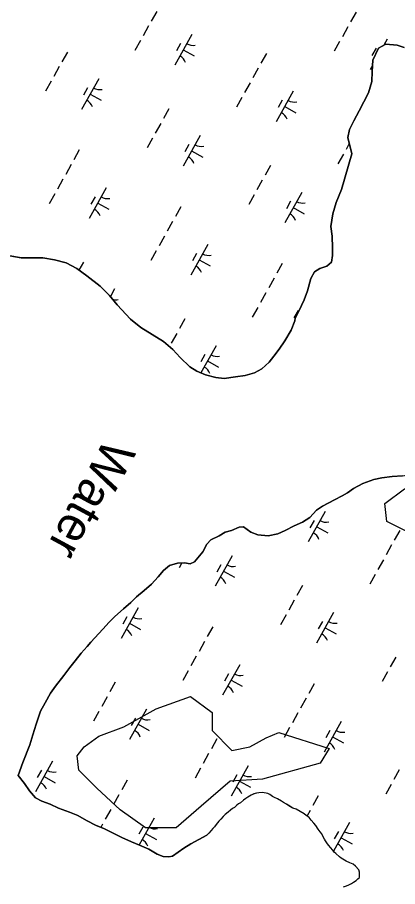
# Model space of a CAD drawing. Extents: x 3923531 to 3943530, y 207391 to 229799.
# Drawn here: x 3935760 to 3936304, y 215274 to 216516 of the extents above; entities that cross this region are included whole.
import ezdxf

# ---------------------------------------------------------------- set-up
doc = ezdxf.new("R2010")
doc.units = 0
for name, color, linetype in [('V-GRID-MAJR', 7, 'Continuous'), ('V-RIVR-IDEN', 7, 'Continuous'), ('V-SITE-VEGE', 7, 'Continuous'), ('V-TOPO-SHOR', 7, 'Continuous'), ('V-WETL-SWMP', 7, 'Continuous')]:
    doc.layers.add(name, color=color, linetype=linetype)

msp = doc.modelspace()

# ---------------------------------------------------------------- linework, layer by layer
at = {"layer": 'V-GRID-MAJR'}
msp.add_spline([(3935779.9, 210874.8), (3935760.8, 211942.6), (3935652.4, 218002.6), (3935544, 224062.6), (3935501.8, 226418.9)], degree=3, dxfattribs=at)
at = {"layer": 'V-SITE-VEGE'}
for points in [[(3936450.2, 215860.4), (3936491.4, 215845), (3936501.7, 215834.7), (3936524.9, 215826.9), (3936548.1, 215824.3), (3936571.2, 215829.5), (3936599.6, 215842.4), (3936620.2, 215821.8), (3936612.4, 215798.6), (3936589.3, 215785.7), (3936550.6, 215772.8), (3936522.3, 215749.6), (3936486.3, 215729), (3936442.5, 215726.4), (3936419.3, 215739.3), (3936367.8, 215759.9), (3936329.2, 215775.4), (3936288, 215796), (3936285.4, 215821.8), (3936313.7, 215842.4), (3936336.9, 215845), (3936393.6, 215842.4)], [(3936066.6, 215468.8), (3936092.3, 215474), (3936115.5, 215486.9), (3936133.5, 215494.6), (3936205.6, 215471.4), (3936192.7, 215450.8), (3936110.3, 215427.6), (3936064, 215425), (3936022.8, 215389), (3935986.7, 215358), (3935943, 215358), (3935906.9, 215383.8), (3935873.4, 215414.7), (3935847.7, 215440.5), (3935845.1, 215461.1), (3935855.4, 215474), (3935876, 215489.4), (3935912.1, 215502.3), (3935958.4, 215528.1), (3936007.3, 215546.1), (3936038.2, 215522.9), (3936038.2, 215497.2)]]:
    msp.add_lwpolyline(points, close=True, dxfattribs=at)
at = {"layer": 'V-TOPO-SHOR'}
for points in [[(3936313.1, 216473.2), (3936303, 216476.7), (3936286.8, 216478.2), (3936276.2, 216472.6), (3936268.1, 216455.3), (3936267.3, 216438.8), (3936266.7, 216424.8), (3936262, 216408.5), (3936255.3, 216395.8), (3936248.6, 216382.6), (3936240.8, 216368.3), (3936234.9, 216356.2), (3936232.2, 216344.8), (3936238.2, 216321.3), (3936223.5, 216270.6), (3936215.7, 216251.9), (3936210.8, 216235.4), (3936208.2, 216217.7), (3936210, 216203.9), (3936210.5, 216187)], [(3936210.5, 216187), (3936210.5, 216176.2), (3936209, 216166.5), (3936202.4, 216160.8), (3936192.6, 216157.3), (3936184.6, 216152.8), (3936179.5, 216143.2), (3936174.5, 216125.4), (3936170, 216112.6), (3936162.3, 216096.4), (3936157.2, 216086.3), (3936156.5, 216082.5), (3936151.4, 216069.2), (3936142.3, 216054.1), (3936134.4, 216042.4), (3936126.7, 216032), (3936119.7, 216023.7), (3936109.2, 216014.2), (3936099, 216008.5), (3936085.6, 216004.5), (3936071.8, 216002.6), (3936055.6, 216000.4), (3936043.5, 216001.5), (3936029, 216005.7), (3936016.3, 216010.6), (3936006.5, 216016.9), (3935992.7, 216030.4), (3935982.1, 216041.8), (3935968.8, 216053.1), (3935952.4, 216063.3), (3935936.4, 216073.4), (3935921.3, 216085.1), (3935902.4, 216105.4), (3935891.4, 216118.9), (3935878.2, 216132.4), (3935859.2, 216146.8), (3935844.7, 216157.3), (3935829.7, 216165.4), (3935812.8, 216169.8), (3935795.9, 216172.7), (3935780.5, 216172.9), (3935765.4, 216172.9), (3935749, 216175.8)], [(3936310.8, 215861.3), (3936295.8, 215860.4), (3936281.1, 215858.4), (3936269.7, 215855.9), (3936253.7, 215850.3), (3936240.6, 215843.2), (3936231.8, 215836.8), (3936224.4, 215832.8), (3936213.2, 215827), (3936196.1, 215817.8), (3936187.5, 215812.3), (3936178.2, 215801.6), (3936167.4, 215794.8), (3936155.8, 215789.7), (3936142.9, 215783.1), (3936132.1, 215778.4), (3936118.3, 215775.7), (3936103.6, 215776.7), (3936093.7, 215780.6), (3936083.2, 215788.3), (3936076.8, 215787.7), (3936066.2, 215783.3), (3936057, 215780.6), (3936048.2, 215775.7), (3936036.3, 215769.8), (3936030.9, 215763.7), (3936025, 215752.6), (3936013.3, 215738.3), (3936007.1, 215735.6), (3935998.7, 215736.9), (3935988.7, 215736.4), (3935977.5, 215732.9), (3935968.5, 215726.1), (3935961, 215716.8), (3935951.5, 215706.3), (3935941.3, 215697.2), (3935930, 215688.4), (3935921.8, 215680.1), (3935911.3, 215671.2), (3935899.2, 215660.4), (3935890.8, 215652.1), (3935881.9, 215642), (3935865, 215623.7), (3935859.3, 215617.3), (3935850.8, 215607.7), (3935842.4, 215597), (3935834.7, 215587.5), (3935826, 215576), (3935814.1, 215560.6), (3935807.2, 215550.5), (3935799.3, 215536.6), (3935792.8, 215524.7), (3935786.4, 215506.4), (3935781.7, 215491.3), (3935777.3, 215476.6), (3935767.7, 215451.4), (3935760.7, 215433)], [(3935760.7, 215433), (3935770.1, 215421.6), (3935777.1, 215411.1), (3935785.7, 215401.1), (3935794.5, 215396.5), (3935806.7, 215391.8), (3935818.7, 215386.5), (3935834.2, 215380.6), (3935846.4, 215375.6), (3935858.8, 215368.7), (3935872.6, 215361.5), (3935883.4, 215357), (3935897.5, 215350.2), (3935909.1, 215344.5), (3935922.9, 215338.4), (3935934.3, 215333.6), (3935947.7, 215327.7), (3935959.8, 215320.7), (3935968.3, 215317), (3935976.6, 215316.6), (3935981.7, 215317.5), (3935997.6, 215329.2), (3936007.6, 215335.2), (3936030.7, 215347.8)], [(3936248.9, 215291.8), (3936249.3, 215294.9), (3936248.2, 215298.1), (3936243.5, 215303.3), (3936240, 215306.1), (3936235.2, 215308.1), (3936230.1, 215310.6), (3936223, 215315), (3936220.3, 215316.6), (3936215.2, 215321.4), (3936212.8, 215323.4), (3936210.9, 215326.2), (3936207.8, 215330.2), (3936205.4, 215333), (3936203.5, 215335.4), (3936200.7, 215339.4), (3936199.2, 215342.1), (3936196.8, 215346.1), (3936195.3, 215349.7), (3936193, 215352.5), (3936190.2, 215356.5), (3936186.7, 215361.3), (3936184, 215364.8), (3936180.1, 215369.2), (3936176.9, 215372.8), (3936173, 215376), (3936169.9, 215378.1), (3936164.4, 215381.3), (3936158.5, 215384.9), (3936153.7, 215386.5), (3936149.4, 215388.9), (3936144.7, 215391.8), (3936140.4, 215394.2), (3936137.6, 215396.2), (3936131.7, 215399.4), (3936127.4, 215401.4), (3936124.6, 215403.1), (3936120.7, 215405.9), (3936117.9, 215407.1), (3936110.4, 215408.7), (3936105.3, 215408.4), (3936101.7, 215407.6), (3936098.1, 215406.9), (3936094.2, 215405), (3936089.4, 215401.8), (3936086.6, 215399.9), (3936083.4, 215397.9), (3936079, 215394), (3936076.2, 215392.5), (3936073.8, 215390.5), (3936070.2, 215387.4), (3936067.5, 215385.8), (3936064.7, 215383.5), (3936061.1, 215380.8), (3936057.1, 215377.2), (3936054.3, 215374.5), (3936050.7, 215370.6), (3936047.9, 215367.8), (3936044.3, 215363.1), (3936041.9, 215359.6), (3936039.1, 215357.2), (3936037.1, 215354.5), (3936033.5, 215350.6), (3936030.7, 215347.8)], [(3936226.2, 215273.8), (3936229, 215275), (3936232.9, 215276.1), (3936237.7, 215278.8), (3936240.5, 215280.4), (3936244.5, 215282.7), (3936246.9, 215285.1), (3936248.9, 215287.4), (3936248.9, 215291.8)]]:
    msp.add_lwpolyline(points, dxfattribs=at)
at = {"layer": 'V-WETL-SWMP'}
for p, q in [((3935959, 216525), (3935951.2, 216511)), ((3936244.2, 216523.8), (3936236.4, 216509.8)), ((3935947.3, 216504.1), (3935939.5, 216490.1)), ((3936232.5, 216502.8), (3936224.6, 216488.8)), ((3936009.2, 216491.9), (3935984.8, 216448.2)), ((3935935.6, 216483.1), (3935927.7, 216469.1)), ((3935993.2, 216479.1), (3935987.4, 216468.6)), ((3936220.7, 216481.9), (3936212.9, 216467.9)), ((3936276.2, 216472.6), (3936286.8, 216478.2)), ((3936288.8, 216485.4), (3936284, 216476.7)), ((3936286.8, 216478.2), (3936303, 216476.7)), ((3935831.3, 216466.9), (3935823.5, 216453)), ((3935997, 216470.1), (3936012.7, 216461.3)), ((3936272.8, 216472.6), (3936267, 216462.1)), ((3936268.1, 216455.3), (3936276.2, 216472.6)), ((3936303, 216476.7), (3936313.1, 216473.2)), ((3936115.9, 216464.8), (3936108.1, 216450.9)), ((3936267.3, 216438.8), (3936268.1, 216455.3)), ((3935819.6, 216446), (3935811.8, 216432)), ((3936104.2, 216443.9), (3936096.4, 216429.9)), ((3936267.7, 216447.6), (3936264.5, 216441.7)), ((3935876, 216428.6), (3935851.6, 216384.9)), ((3936266.7, 216424.8), (3936267.3, 216438.8)), ((3935807.9, 216425), (3935800.1, 216411.1)), ((3935860, 216415.7), (3935854.2, 216405.3)), ((3936092.5, 216422.9), (3936084.7, 216409)), ((3936262, 216408.5), (3936266.7, 216424.8)), ((3935863.8, 216406.7), (3935879.5, 216398)), ((3936154.4, 216410.8), (3936130, 216367.1)), ((3936255.3, 216395.8), (3936262, 216408.5)), ((3936080.8, 216402), (3936073, 216388)), ((3936138.4, 216397.9), (3936132.6, 216387.5)), ((3936248.6, 216382.6), (3936255.3, 216395.8)), ((3935976.6, 216385.8), (3935968.7, 216371.8)), ((3936142.2, 216388.9), (3936158, 216380.1)), ((3936240.8, 216368.3), (3936248.6, 216382.6)), ((3936234.9, 216356.2), (3936240.8, 216368.3)), ((3935964.8, 216364.9), (3935957, 216350.9)), ((3936232.2, 216344.8), (3936234.9, 216356.2)), ((3935953.1, 216343.9), (3935945.3, 216329.9)), ((3936021.2, 216347.4), (3935996.8, 216303.8)), ((3936238.2, 216321.3), (3936232.2, 216344.8)), ((3936005.2, 216334.6), (3935999.4, 216324.1)), ((3936234.4, 216336), (3936229.9, 216327.8)), ((3935848.3, 216326.9), (3935840.5, 216312.9)), ((3936009, 216325.6), (3936024.8, 216316.8)), ((3936226, 216320.9), (3936218.2, 216306.9)), ((3936223.5, 216270.6), (3936238.2, 216321.3)), ((3935836.6, 216305.9), (3935828.8, 216292)), ((3936121.8, 216304.7), (3936114, 216290.7)), ((3935824.9, 216285), (3935817.1, 216271)), ((3936110.1, 216283.7), (3936102.3, 216269.8)), ((3935886.8, 216272.8), (3935862.4, 216229.1)), ((3936166.4, 216266.3), (3936142.1, 216222.7)), ((3936215.7, 216251.9), (3936223.5, 216270.6)), ((3935813.2, 216264), (3935805.4, 216250.1)), ((3935870.8, 216260), (3935865, 216249.5)), ((3936098.4, 216262.8), (3936090.6, 216248.8)), ((3935874.6, 216251), (3935890.3, 216242.2)), ((3935993.5, 216245.8), (3935985.7, 216231.8)), ((3936150.4, 216253.5), (3936144.6, 216243)), ((3936154.3, 216244.5), (3936170, 216235.7)), ((3936210.8, 216235.4), (3936215.7, 216251.9)), ((3936208.2, 216217.7), (3936210.8, 216235.4)), ((3935981.8, 216224.8), (3935974, 216210.8)), ((3936210, 216203.9), (3936208.2, 216217.7)), ((3935970.1, 216203.9), (3935962.3, 216189.9)), ((3936032, 216191.7), (3936007.7, 216148)), ((3936210.5, 216187), (3936210, 216203.9)), ((3935958.4, 216182.9), (3935950.6, 216168.9)), ((3936210.5, 216176.2), (3936210.5, 216187)), ((3935749, 216175.8), (3935765.3, 216172.9)), ((3935765.3, 216172.9), (3935780.5, 216172.9)), ((3935780.5, 216172.9), (3935795.9, 216172.7)), ((3935795.9, 216172.7), (3935812.8, 216169.8)), ((3935812.8, 216169.8), (3935829.7, 216165.4)), ((3936016, 216178.8), (3936010.2, 216168.4)), ((3936019.8, 216169.8), (3936035.6, 216161.1)), ((3936209, 216166.5), (3936210.5, 216176.2)), ((3935829.7, 216165.4), (3935844.7, 216157.3)), ((3935844.7, 216157.3), (3935859.2, 216146.8)), ((3935854.2, 216166.7), (3935847.7, 216155.1)), ((3936138.7, 216164.6), (3936130.9, 216150.7)), ((3936184.6, 216152.8), (3936192.6, 216157.3)), ((3936192.6, 216157.3), (3936202.4, 216160.8)), ((3936202.4, 216160.8), (3936209, 216166.5)), ((3935859.2, 216146.8), (3935878.2, 216132.4)), ((3936127, 216143.7), (3936119.2, 216129.7)), ((3936174.5, 216125.4), (3936179.5, 216143.2)), ((3936179.5, 216143.2), (3936184.6, 216152.8)), ((3935878.2, 216132.4), (3935891.4, 216118.9)), ((3935891.4, 216118.9), (3935902.4, 216105.4)), ((3935898.8, 216128.4), (3935892.7, 216117.3)), ((3936115.3, 216122.7), (3936107.5, 216108.8)), ((3936170, 216112.6), (3936174.5, 216125.4)), ((3935902.4, 216105.4), (3935921.3, 216085.1)), ((3936162.3, 216096.4), (3936170, 216112.6)), ((3936103.6, 216101.8), (3936095.8, 216087.8)), ((3936161.2, 216097.7), (3936155.4, 216087.2)), ((3936157.2, 216086.3), (3936162.3, 216096.4)), ((3935921.3, 216085.1), (3935936.4, 216073.4)), ((3935999.4, 216085.6), (3935991.6, 216071.6)), ((3936151.4, 216069.2), (3936156.5, 216082.5)), ((3936156.5, 216082.5), (3936157.2, 216086.3)), ((3935936.4, 216073.4), (3935952.4, 216063.3)), ((3936142.3, 216054.1), (3936151.4, 216069.2)), ((3935952.4, 216063.3), (3935968.8, 216053.1)), ((3935987.7, 216064.6), (3935979.9, 216050.7)), ((3935968.8, 216053.1), (3935982.1, 216041.8)), ((3936044.1, 216047.2), (3936022.3, 216008.2)), ((3936134.4, 216042.4), (3936142.3, 216054.1)), ((3935982.1, 216041.8), (3935992.7, 216030.4)), ((3935992.7, 216030.4), (3936006.5, 216016.9)), ((3936028, 216034.4), (3936022.2, 216023.9)), ((3936119.7, 216023.7), (3936126.7, 216032)), ((3936126.7, 216032), (3936134.4, 216042.4)), ((3936031.9, 216025.4), (3936047.6, 216016.6)), ((3936109.2, 216014.2), (3936119.7, 216023.7)), ((3936006.5, 216016.9), (3936016.3, 216010.6)), ((3936016.3, 216010.6), (3936029, 216005.7)), ((3936029, 216005.7), (3936043.5, 216001.5)), ((3936085.6, 216004.5), (3936099, 216008.5)), ((3936099, 216008.5), (3936109.2, 216014.2)), ((3936043.5, 216001.5), (3936055.6, 216000.4)), ((3936055.6, 216000.4), (3936071.8, 216002.6)), ((3936071.8, 216002.6), (3936085.6, 216004.5)), ((3936200.1, 215810.3), (3936175.7, 215766.7)), ((3936184.1, 215797.5), (3936178.2, 215787)), ((3936187.9, 215788.5), (3936203.6, 215779.7)), ((3936306.7, 215783.3), (3936298.9, 215769.3)), ((3936295, 215762.4), (3936287.2, 215748.4)), ((3936066.9, 215747), (3936042.5, 215703.4)), ((3935995, 215736.7), (3935991, 215729.5)), ((3936050.9, 215734.2), (3936045, 215723.7)), ((3936283.3, 215741.4), (3936275.5, 215727.4)), ((3936054.7, 215725.2), (3936070.4, 215716.4)), ((3936271.6, 215720.4), (3936263.8, 215706.5)), ((3936167.4, 215704.3), (3936159.6, 215690.3)), ((3936155.7, 215683.3), (3936147.9, 215669.3)), ((3935932.5, 215672.4), (3935908.1, 215628.7)), ((3935916.5, 215659.6), (3935910.6, 215649.1)), ((3936144, 215662.4), (3936136.2, 215648.4)), ((3936212.1, 215665.9), (3936187.7, 215622.2)), ((3935920.3, 215650.5), (3935936, 215641.8)), ((3936039.1, 215645.3), (3936031.3, 215631.4)), ((3936196.1, 215653.1), (3936190.2, 215642.6)), ((3936199.9, 215644.1), (3936215.6, 215635.3)), ((3936027.4, 215624.4), (3936019.6, 215610.4)), ((3936015.7, 215603.4), (3936007.9, 215589.5)), ((3936300.9, 215602.2), (3936293.1, 215588.2)), ((3936077.7, 215591.3), (3936053.3, 215547.6)), ((3936004, 215582.5), (3935996.2, 215568.5)), ((3936061.7, 215578.4), (3936055.8, 215568)), ((3936289.2, 215581.2), (3936281.4, 215567.3)), ((3935899.8, 215566.3), (3935892, 215552.3)), ((3936065.5, 215569.4), (3936081.2, 215560.6)), ((3936184.3, 215564.2), (3936176.5, 215550.3)), ((3935888.1, 215545.4), (3935880.3, 215531.4)), ((3936172.6, 215543.3), (3936164.8, 215529.3)), ((3935876.4, 215524.4), (3935868.6, 215510.4)), ((3935944.5, 215527.9), (3935920.1, 215484.3)), ((3936160.9, 215522.3), (3936153.1, 215508.3)), ((3935928.5, 215515.1), (3935922.6, 215504.6)), ((3936222.9, 215510.1), (3936198.5, 215466.5)), ((3935932.3, 215506.1), (3935948, 215497.3)), ((3936149.2, 215501.4), (3936141.4, 215487.4)), ((3936206.9, 215497.3), (3936201, 215486.8)), ((3936045, 215485.2), (3936037.2, 215471.2)), ((3936210.7, 215488.3), (3936226.4, 215479.5)), ((3936033.3, 215464.2), (3936025.5, 215450.3)), ((3935810.1, 215453.3), (3935785.7, 215409.6)), ((3936089.7, 215446.8), (3936065.3, 215403.2)), ((3935794.1, 215440.5), (3935788.2, 215430)), ((3936021.6, 215443.3), (3936013.8, 215429.3)), ((3936073.7, 215434), (3936067.8, 215423.5)), ((3936306.1, 215441.2), (3936298.3, 215427.2)), ((3935797.9, 215431.5), (3935813.6, 215422.7)), ((3935916.7, 215426.3), (3935908.9, 215412.3)), ((3936077.5, 215425), (3936093.2, 215416.2)), ((3936294.4, 215420.2), (3936286.6, 215406.3)), ((3935905, 215405.3), (3935897.2, 215391.3)), ((3936190.2, 215404.1), (3936182.4, 215390.1)), ((3935893.3, 215384.4), (3935885.5, 215370.4)), ((3935955.3, 215372.2), (3935933.8, 215333.8)), ((3936178.5, 215383.1), (3936174.1, 215375.2)), ((3935881.6, 215363.4), (3935879.1, 215358.8)), ((3935939.3, 215359.3), (3935933.4, 215348.9)), ((3936234.9, 215365.7), (3936212, 215324.6)), ((3935943.1, 215350.3), (3935958.8, 215341.6)), ((3936218.9, 215352.9), (3936213.1, 215342.4)), ((3936222.7, 215343.9), (3936238.4, 215335.1))]:
    msp.add_line(p, q, dxfattribs=at)
for points in [[(3936295.8, 215860.4), (3936310.8, 215861.3), (3936326, 215863.5), (3936340.2, 215866.5), (3936368.7, 215870.2), (3936380.7, 215875.9), (3936393.3, 215882.1), (3936401.4, 215885.8), (3936408.2, 215894.5), (3936412.1, 215901.1), (3936415.8, 215912.6), (3936417.7, 215921), (3936422.5, 215930.3), (3936435.8, 215943.5), (3936439.9, 215954.2)], [(3936101.7, 215407.6), (3936098.2, 215406.9), (3936094.2, 215405), (3936089.4, 215401.8), (3936086.6, 215399.9), (3936083.4, 215397.9), (3936079, 215394), (3936076.2, 215392.5), (3936073.8, 215390.5), (3936070.2, 215387.4), (3936067.5, 215385.8), (3936064.7, 215383.5), (3936061.1, 215380.8), (3936057.1, 215377.2), (3936054.3, 215374.5), (3936050.7, 215370.6), (3936047.9, 215367.8), (3936044.3, 215363.1), (3936041.9, 215359.6), (3936039.1, 215357.2), (3936037.1, 215354.5), (3936033.5, 215350.6), (3936030.7, 215347.8), (3936007.6, 215335.2), (3935997.6, 215329.2), (3935981.7, 215317.5), (3935976.6, 215316.6), (3935968.3, 215317), (3935959.8, 215320.7), (3935947.7, 215327.7), (3935934.3, 215333.6), (3935922.9, 215338.4), (3935909.1, 215344.5), (3935897.5, 215350.2), (3935883.4, 215357), (3935872.6, 215361.5), (3935858.8, 215368.7), (3935846.4, 215375.6), (3935834.2, 215380.6), (3935818.7, 215386.5), (3935806.7, 215391.8), (3935794.5, 215396.5), (3935785.7, 215401.1), (3935777.1, 215411.1), (3935770.1, 215421.6), (3935760.7, 215433), (3935767.7, 215451.4), (3935777.3, 215476.6), (3935781.7, 215491.3), (3935786.4, 215506.5), (3935792.8, 215524.7), (3935799.3, 215536.6), (3935807.2, 215550.5), (3935814.1, 215560.6), (3935826, 215576), (3935834.7, 215587.5), (3935842.4, 215597), (3935850.8, 215607.7), (3935859.3, 215617.3), (3935865, 215623.7), (3935881.9, 215642), (3935890.8, 215652.1), (3935899.2, 215660.4), (3935911.3, 215671.2), (3935921.8, 215680.1), (3935930, 215688.4), (3935941.3, 215697.2), (3935951.5, 215706.3), (3935961, 215716.8), (3935968.5, 215726), (3935977.5, 215732.9), (3935988.7, 215736.4), (3935998.7, 215736.9), (3936007.1, 215735.6), (3936013.3, 215738.3), (3936025, 215752.6), (3936030.9, 215763.7), (3936036.3, 215769.8), (3936048.2, 215775.7), (3936057, 215780.6), (3936066.2, 215783.2), (3936076.8, 215787.7), (3936083.2, 215788.3), (3936093.7, 215780.6), (3936103.6, 215776.7), (3936118.3, 215775.7), (3936132.1, 215778.4), (3936142.9, 215783.1), (3936155.8, 215789.7), (3936167.4, 215794.8), (3936178.2, 215801.6), (3936187.5, 215812.3), (3936196.1, 215817.8), (3936213.2, 215827), (3936224.4, 215832.8), (3936231.8, 215836.8), (3936240.6, 215843.2), (3936253.7, 215850.3), (3936269.7, 215855.9), (3936281.1, 215858.4), (3936295.8, 215860.4)], [(3936226.2, 215273.8), (3936229, 215275), (3936232.9, 215276.1), (3936237.7, 215278.8), (3936240.5, 215280.4), (3936244.5, 215282.7), (3936246.9, 215285.1), (3936248.9, 215287.4), (3936248.9, 215291.8), (3936249.3, 215294.9), (3936248.2, 215298.1), (3936243.5, 215303.3), (3936240, 215306.1), (3936235.2, 215308.1), (3936230.1, 215310.6), (3936223, 215315), (3936220.3, 215316.6), (3936215.2, 215321.4), (3936212.8, 215323.4), (3936210.9, 215326.2), (3936207.8, 215330.2), (3936205.4, 215333), (3936203.5, 215335.4), (3936200.7, 215339.4), (3936199.2, 215342.1), (3936196.8, 215346.1), (3936195.3, 215349.7), (3936193, 215352.5), (3936190.2, 215356.5), (3936186.7, 215361.3), (3936184, 215364.8), (3936180.1, 215369.2), (3936176.9, 215372.8), (3936173, 215376), (3936169.9, 215378.1), (3936164.4, 215381.3), (3936158.5, 215384.9), (3936153.7, 215386.5), (3936149.4, 215389), (3936144.7, 215391.8), (3936140.4, 215394.2), (3936137.6, 215396.2), (3936131.7, 215399.4), (3936127.4, 215401.4), (3936124.6, 215403.1), (3936120.7, 215405.9), (3936117.9, 215407.1), (3936110.4, 215408.7), (3936105.3, 215408.4), (3936101.7, 215407.6)]]:
    msp.add_lwpolyline(points, dxfattribs=at)
for centre, start, end in [((3936010.7, 216494), 240.0381, 281.5817), ((3935983.8, 216445.8), 20.0381, 61.5817), ((3935877.5, 216430.7), 240.0381, 281.5817), ((3935850.6, 216382.5), 20.0381, 61.5817), ((3936155.9, 216412.9), 240.0381, 281.5817), ((3936129, 216364.7), 20.0381, 61.5817), ((3936022.7, 216349.6), 240.0381, 281.5817), ((3935995.8, 216301.4), 20.0381, 61.5817), ((3935888.3, 216275), 240.0381, 281.5817), ((3935861.4, 216226.7), 20.0381, 61.5817), ((3936167.9, 216268.5), 240.0381, 281.5817), ((3936141, 216220.3), 20.0381, 61.5817), ((3936033.5, 216193.8), 240.0381, 281.5817), ((3936006.6, 216145.6), 20.0381, 61.5817), ((3935900.3, 216130.5), 255.2144, 281.5817), ((3936045.5, 216049.4), 240.0381, 281.5817), ((3936018.6, 216001.2), 20.0381, 61.5817), ((3936201.6, 215812.5), 240.0381, 281.5817), ((3936174.6, 215764.3), 20.0381, 61.5817), ((3936068.4, 215749.2), 240.0381, 281.5817), ((3936041.4, 215701), 20.0381, 61.5817), ((3935934, 215674.5), 240.0381, 281.5817), ((3936213.6, 215668.1), 240.0381, 281.5817), ((3935907, 215626.3), 20.0381, 61.5817), ((3936186.6, 215619.8), 20.0381, 61.5817), ((3936079.2, 215593.4), 240.0381, 281.5817), ((3936052.2, 215545.2), 20.0381, 61.5817), ((3935946, 215530.1), 240.0381, 281.5817), ((3935919, 215481.9), 20.0381, 61.5817), ((3936224.4, 215512.3), 240.0381, 281.5817), ((3936197.4, 215464.1), 20.0381, 61.5817), ((3935811.6, 215455.5), 240.0381, 281.5817), ((3935784.6, 215407.2), 20.0381, 61.5817), ((3936091.2, 215449), 240.0381, 281.5817), ((3936064.2, 215400.8), 20.0381, 61.5817), ((3935956.8, 215374.3), 240.0381, 281.5817), ((3936236.4, 215367.9), 240.0381, 281.5817), ((3935929.8, 215326.1), 20.0381, 61.5817), ((3936209.5, 215319.6), 20.0381, 61.5817)]:
    msp.add_arc(centre, 17.6, start, end, dxfattribs=at)

# ---------------------------------------------------------------- texts
at = {"layer": 'V-RIVR-IDEN'}
msp.add_text('Water', height=50, rotation=241.5894, dxfattribs=at).set_placement((3935885.9, 215917.1))

doc.saveas('drawing.dxf')
